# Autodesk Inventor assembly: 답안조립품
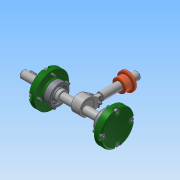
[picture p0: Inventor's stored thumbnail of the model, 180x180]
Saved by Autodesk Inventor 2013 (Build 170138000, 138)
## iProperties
Created: 2016-02
Part Number: 답안조립품
Document SubType Name: Assembly
Designer: Administrator
Author: Administrator
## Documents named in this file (16)
- C:\Users\Administrator\Desktop\460212V1006\답안조립품.iam
- C:\Users\Administrator\Desktop\460212V1006\V벨트풀리.ipt
- C:\Users\Administrator\Desktop\460212V1006\고정핀 1.2 x 10.ipt
- C:\Users\Administrator\Desktop\460212V1006\뒤커버.ipt
- C:\Users\Administrator\Desktop\460212V1006\링크.ipt
- C:\Users\Administrator\Desktop\460212V1006\멈춤나사 M3x8.ipt
- C:\Users\Administrator\Desktop\460212V1006\베어링 12 x 32 x 10.ipt
- C:\Users\Administrator\Desktop\460212V1006\본체.ipt
- C:\Users\Administrator\Desktop\460212V1006\볼트 M4 x 12.ipt
- C:\Users\Administrator\Desktop\460212V1006\부시.ipt
- C:\Users\Administrator\Desktop\460212V1006\슬라이드.ipt
- C:\Users\Administrator\Desktop\460212V1006\앞커버.ipt
- C:\Users\Administrator\Desktop\460212V1006\오일실 12 25 7.ipt
- C:\Users\Administrator\Desktop\460212V1006\키 4 x 4 x 10.ipt
- C:\Users\Administrator\Desktop\460212V1006\편심축.ipt
- C:\Users\Administrator\Desktop\460212V1006\핀 5 x 18.ipt
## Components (11 placed, 4 different names)
1. V벨트풀리:1 — 플러쉬:2
2. 고정핀 1.2 x 10:1
3. 핀 5 x 18:1
4. ISO 4762 M4 x 12:2
5. ISO 4762 M4 x 12:3
6. ISO 4762 M4 x 12:4
7. ISO 4762 M4 x 12:5
8. ISO 4762 M4 x 12:1
9. ISO 4762 M4 x 12:6
10. ISO 4762 M4 x 12:7
11. ISO 4762 M4 x 12:8
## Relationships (1: Flush 1)
- 플러쉬:2 [Flush]: V벨트풀리:1
